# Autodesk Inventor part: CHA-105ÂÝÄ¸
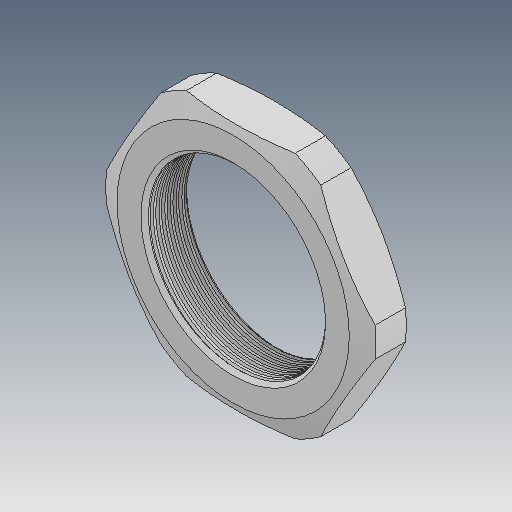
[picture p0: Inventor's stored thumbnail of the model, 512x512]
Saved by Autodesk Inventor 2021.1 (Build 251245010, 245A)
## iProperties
Created: 2019-12
Part Number: CHA-105ÂÝÄ¸
Material: Ogólny
Document SubType Name: Modeling
Designer: user
Density: 1 g/cm^3
Appearance: Domyślna
Author: user
Revision Number: ÈÎºÎ
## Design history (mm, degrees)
feature "ÊäÈë1"
node "Bryła1"
